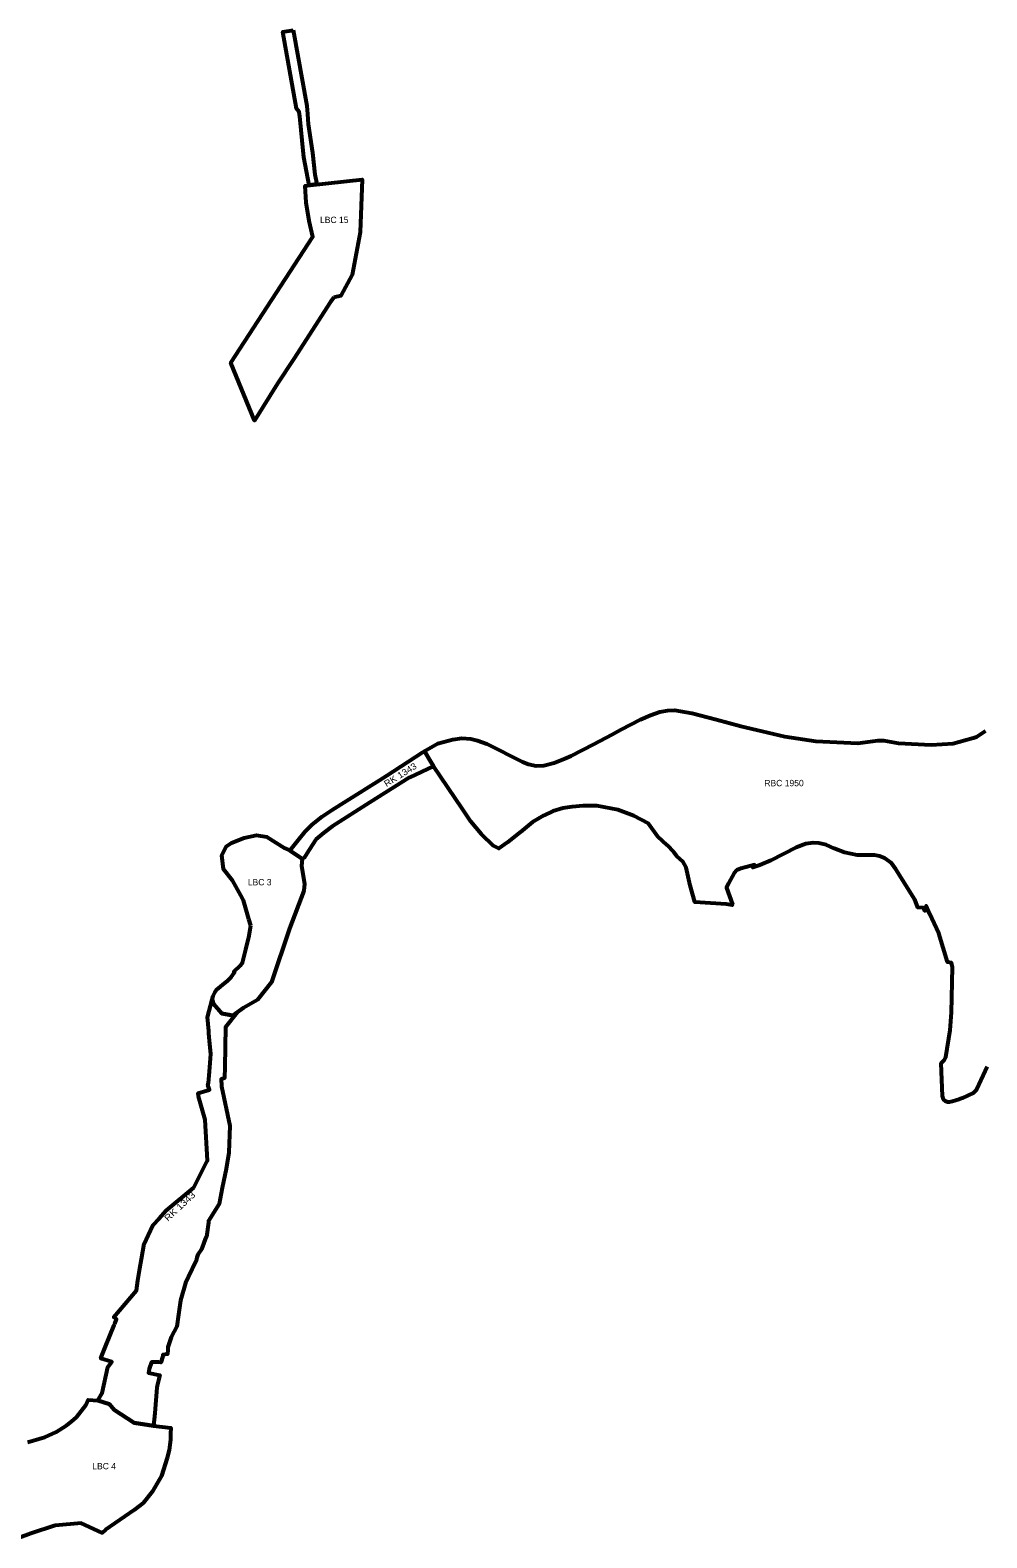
# Model space of a CAD drawing. Extents: x -650276 to -642570, y -1074314 to -1066553.
# Drawn here: x -646294 to -644496, y -1070338 to -1067504 of the extents above; entities that cross this region are included whole.
import ezdxf
from ezdxf.enums import TextEntityAlignment as Align

# ---------------------------------------------------------------- set-up
doc = ezdxf.new("R2010")
doc.units = 0
doc.header["$LTSCALE"] = 4.8
for name, color, linetype, lineweight in [('15', 7, 'Continuous', 53), ('19', 7, 'Continuous', 53), ('23', 7, 'Continuous', 53), ('27', 7, 'Continuous', 53)]:
    doc.layers.add(name, color=color, linetype=linetype, lineweight=lineweight)
doc.layers.add('63', color=7, linetype='Continuous')

msp = doc.modelspace()

# ---------------------------------------------------------------- linework, layer by layer
at = {"layer": '15'}
for points in [[(-645275.45, -1068964.38), (-645292.77, -1068966.91), (-645311.99, -1068972.74), (-645328.55, -1068980.37), (-645350.17, -1068993.33), (-645372.67, -1069011.7), (-645371.56, -1069010.81), (-645396.53, -1069030.88), (-645413.29, -1069042.92), (-645423.51, -1069037.41), (-645446.14, -1069015.65), (-645466.03, -1068991.95), (-645482.49, -1068967.44), (-645535.87, -1068888.03), (-645540.97, -1068879.83), (-645553.3, -1068860.01), (-645527.84, -1068845.59), (-645499.8, -1068838.07), (-645482.88, -1068835.58), (-645466.2, -1068836.84), (-645453.59, -1068839.38), (-645436.18, -1068845.91), (-645369.07, -1068879.97), (-645357.42, -1068884.27), (-645342.95, -1068887.14), (-645328.6, -1068886.89), (-645309.08, -1068881.71), (-645290.63, -1068873.98), (-645277.52, -1068868.49), (-645234.68, -1068846.67), (-645200.52, -1068828.2), (-645183.29, -1068819.23), (-645146.79, -1068800.21), (-645128.2, -1068792.33), (-645110.5, -1068786.08), (-645096.42, -1068783.56), (-645082.62, -1068782.8), (-645050.5, -1068788.01), (-645004.48, -1068800.3), (-644958.68, -1068812.54), (-644928.99, -1068819.58), (-644875.93, -1068832.15), (-644817.51, -1068840.81), (-644738.26, -1068844.61), (-644700.9, -1068839.57), (-644689.35, -1068839.45), (-644661.88, -1068844.68), (-644600.36, -1068847.65), (-644558.97, -1068845.61), (-644521.21, -1068834.8), (-644515.35, -1068832.94), (-644498.216, -1068821.641)], [(-644495.46, -1069453.11), (-644514.85, -1069495), (-644517.06, -1069498.44), (-644520.98, -1069501.79), (-644542.01, -1069512), (-644548.78, -1069514.21), (-644561.24, -1069518.27), (-644566.01, -1069519.75), (-644569.16, -1069519.63), (-644572.75, -1069518.39), (-644577.16, -1069514.36), (-644579.1, -1069508.42), (-644581.87, -1069446.28), (-644575.93, -1069440.66), (-644572.97, -1069435.12), (-644565.02, -1069383.98), (-644562.55, -1069350.97), (-644560.58, -1069265.94), (-644562.47, -1069257.56), (-644569.73, -1069256.28), (-644586.03, -1069202.7), (-644603.57, -1069164.82), (-644610.16, -1069150.6), (-644612.86, -1069156.82), (-644612.3, -1069159.66), (-644613.58, -1069155.95), (-644615.11, -1069154.11), (-644625.34, -1069153.31), (-644631.12, -1069138.5), (-644666.82, -1069081.36), (-644675.02, -1069070.3), (-644688.27, -1069060.62), (-644697.5, -1069057.16), (-644706.99, -1069055.45), (-644739.62, -1069055.42), (-644763.63, -1069050.17), (-644783.05, -1069042.69), (-644797.84, -1069035.56), (-644811.66, -1069032.56), (-644822.43, -1069031.81), (-644836.38, -1069033.69), (-644854.3, -1069040.5), (-644901.69, -1069064.96), (-644922.7, -1069073.95), (-644935.81, -1069078.12), (-644932.95, -1069073.65), (-644958.25, -1069079.99), (-644965.95, -1069083.67), (-644970.84, -1069088.8), (-644981.3, -1069108.22), (-644985.15, -1069116.67), (-644974.34, -1069147.85), (-644974.505, -1069149.05), (-644986.221, -1069147.139), (-645044.97, -1069143.38), (-645053.61, -1069112.32), (-645061.2, -1069078.47), (-645067.57, -1069067.16), (-645078.47, -1069057.37), (-645084.19, -1069049.55), (-645096.97, -1069036.63), (-645114.52, -1069020.11), (-645131.73, -1068995.69), (-645159.37, -1068981.11), (-645189.84, -1068969.91), (-645229.27, -1068962.28), (-645255.21, -1068962.49), (-645275.45, -1068964.38)]]:
    msp.add_lwpolyline(points, dxfattribs=at)
at = {"layer": '19'}
for points in [[(-645806.26, -1069046.58), (-645803.29, -1069042.92), (-645790.53, -1069027.19), (-645777.16, -1069010.72), (-645770.47, -1069003.97), (-645764.17, -1068997.62), (-645745.65, -1068982.8), (-645726.46, -1068970.04), (-645699.5, -1068953.13), (-645637.82, -1068914.25), (-645630.48, -1068909.6), (-645623.92, -1068905.45), (-645557.17, -1068862.39), (-645553.3, -1068860.01), (-645540.97, -1068879.83), (-645535.87, -1068888.03), (-645581.58, -1068909.41), (-645655.69, -1068956.35), (-645726.85, -1069001.34), (-645742.5, -1069012.99), (-645757.51, -1069026.02), (-645770.04, -1069045.34), (-645777.73, -1069057.2), (-645779.49, -1069059.92), (-645783.02, -1069061.84), (-645784.69, -1069060.74)], [(-646167.42, -1070080.12), (-646159.14, -1070066.71), (-646148.34, -1070017.73), (-646141.14, -1070007.63), (-646161.71, -1070001.55), (-646160.09, -1069997.51), (-646152.59, -1069978.9), (-646136.46, -1069938.84), (-646135.28, -1069935.88), (-646131.96, -1069927.57), (-646136.23, -1069923.94), (-646136.88, -1069923.39), (-646094.82, -1069873.63), (-646091.72, -1069854.99), (-646088.02, -1069832.44), (-646085.07, -1069814.68), (-646080.14, -1069785.63), (-646072.6, -1069769.62), (-646063.59, -1069750.57), (-646051.95, -1069738.02), (-646038.48, -1069723.16), (-645986.71, -1069679.91), (-645961.36, -1069630.05), (-645960.78, -1069628.91), (-645965.36, -1069552.99), (-645977.73, -1069509.11), (-645978.852, -1069502.689), (-645957.35, -1069496.35), (-645958.57, -1069492.51), (-645960.18, -1069487.45), (-645959.32, -1069483.43), (-645959.32, -1069483.43), (-645957.52, -1069461.75), (-645955.52, -1069437.7), (-645954.74, -1069428.36), (-645956.97, -1069404), (-645958.23, -1069390.23), (-645958.59, -1069386.32), (-645961.03, -1069359.69), (-645952.303, -1069326.378), (-645949.992, -1069334.461), (-645933.792, -1069352.53), (-645913.23, -1069356.892), (-645905.079, -1069350.779), (-645926.91, -1069378.79), (-645928.53, -1069453.3), (-645928.99, -1069474.55), (-645935.05, -1069476.32), (-645935.03, -1069480.02), (-645935, -1069485.04), (-645934.97, -1069490.31), (-645918.82, -1069563.81), (-645921.18, -1069613.78), (-645925.69, -1069644.69), (-645933.68, -1069680.28), (-645939.36, -1069710.47), (-645958.9, -1069742.7), (-645959.35, -1069745.74), (-645963.06, -1069772.82), (-645964.34, -1069773.6), (-645967.15, -1069781.97), (-645968.57, -1069785.9), (-645972.16, -1069795.77), (-645979.38, -1069805.93), (-645980.87, -1069811.56), (-645982.12, -1069817.85), (-645996.72, -1069847.96), (-646002.25, -1069859.77), (-646011.51, -1069892.38), (-646015.46, -1069918.63), (-646018.88, -1069941.32), (-646029.65, -1069960.92), (-646035.42, -1069980.12), (-646035.75, -1069984.73), (-646036.36, -1069993.34), (-646045.27, -1069994.44), (-646045.22, -1069996.81), (-646048.71, -1070008.77), (-646053.4, -1070007.98), (-646066.06, -1070008.11), (-646070.67, -1070020.78), (-646071.32, -1070024.95), (-646071.84, -1070028.3), (-646050.67, -1070032.37), (-646052.63, -1070039.21), (-646055.78, -1070052.52), (-646056.09, -1070055.76), (-646060.36, -1070103.99), (-646062.8, -1070128.04), (-646098.96, -1070122.04), (-646136.41, -1070097.53), (-646145.47, -1070087.27)]]:
    msp.add_lwpolyline(points, close=True, dxfattribs=at)
at = {"layer": '23'}
for points in [[(-645723.79, -1068007.07), (-645729.57, -1068015.25), (-645798.69, -1068122.17), (-645829.66, -1068168.34), (-645872.64, -1068238.08), (-645917.44, -1068129.99), (-645763.31, -1067892.76), (-645769.95, -1067862.62), (-645775.45, -1067828.44), (-645777.308, -1067797.119), (-645768.11, -1067795.54), (-645670.064, -1067785.335), (-645673.827, -1067884.119), (-645688.88, -1067964.087), (-645710.519, -1068003.601)], [(-645879.84, -1069187.64), (-645883.39, -1069175.24), (-645893.36, -1069140.52), (-645898.3, -1069130.96), (-645913.85, -1069102.71), (-645930.96, -1069081.23), (-645933.84, -1069055.44), (-645925.49, -1069038.22), (-645915.93, -1069031.93), (-645892.13, -1069022.51), (-645868.65, -1069017.82), (-645849.73, -1069020.52), (-645815.87, -1069041.86), (-645806.26, -1069046.58), (-645784.69, -1069060.74), (-645783.02, -1069061.84), (-645784.52, -1069075.66), (-645778.75, -1069108.98), (-645779.685, -1069122.296), (-645806.806, -1069193.112), (-645840.644, -1069294.052), (-645867.026, -1069327.317), (-645893.291, -1069341.938), (-645913.23, -1069356.892), (-645933.792, -1069352.53), (-645949.992, -1069334.461), (-645952.303, -1069326.378), (-645950.49, -1069319.46), (-645947.21, -1069313.26), (-645943.67, -1069307.84), (-645936.46, -1069301.94), (-645932.07, -1069298.43), (-645923.56, -1069291.6), (-645916.39, -1069284.67), (-645910.4, -1069275.66), (-645911.64, -1069274.48), (-645898.96, -1069262.45), (-645898.67, -1069262.02), (-645895.95, -1069257.98), (-645895.25, -1069257.41), (-645888.98, -1069232.44), (-645882.56, -1069206.54)]]:
    msp.add_lwpolyline(points, close=True, dxfattribs=at)
msp.add_lwpolyline([(-646298.56, -1070158.26), (-646266.83, -1070149.27), (-646245.94, -1070139.49), (-646225.41, -1070126.72), (-646215.99, -1070118.79), (-646207.09, -1070111.31), (-646189.94, -1070089.25), (-646185.32, -1070079.18), (-646167.42, -1070080.12), (-646145.47, -1070087.27), (-646136.41, -1070097.53), (-646098.96, -1070122.04), (-646062.8, -1070128.04), (-646029.864, -1070131.413), (-646030.51, -1070143.17), (-646030.66, -1070153.86), (-646033.06, -1070173.32), (-646036.61, -1070187.84), (-646047.55, -1070221.59), (-646064.78, -1070252.22), (-646081.74, -1070273.1), (-646098.57, -1070285.71), (-646152.57, -1070323.39), (-646159.26, -1070328.75), (-646198.52, -1070310.669), (-646247.667, -1070315.004), (-646293.14, -1070330.3), (-646314.84, -1070338.41)], dxfattribs=at)
at = {"layer": '27'}
msp.add_lwpolyline([(-645799.72, -1067504.47), (-645774.48, -1067646.99), (-645773.23, -1067662.67), (-645771.86, -1067680.92), (-645763.92, -1067735.14), (-645759.32, -1067775.89), (-645755.758, -1067794.254), (-645769.602, -1067795.796), (-645779.64, -1067743.41), (-645780.39, -1067737.84), (-645787.55, -1067666.46), (-645788.395, -1067658.038), (-645793.94, -1067651.61), (-645819.48, -1067507.57)], close=True, dxfattribs=at)

# ---------------------------------------------------------------- texts
at = {"layer": '63'}
for s, p in [('LBC 15', (-645722.709, -1067867.044)), ('RBC 1950', (-644877.184, -1068925.671)), ('LBC 3', (-645862.946, -1069111.949)), ('LBC 4', (-646155.337, -1070209.573))]:
    msp.add_text(s, height=12, dxfattribs=at).set_placement(p, align=Align.CENTER)
for rotation, width, p in [(32.163, 1.1, (-645595.379, -1068909.273)), (42.958, 1.15, (-646009.018, -1069719.932))]:
    msp.add_text('RK 1343', height=12, rotation=rotation, dxfattribs=dict(at, width=width)).set_placement(p, align=Align.CENTER)

doc.saveas('drawing.dxf')
